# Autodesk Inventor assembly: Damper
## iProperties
Shininess: 20.0
Length Units: 11269
Angle Units: 11279
Time Units: 11290
Mass Units: 11283
Length Display Precision: 3
Angle Display Precision: 2
Created: 2001-04
Part Number: Damper
Document SubType Name: Baugruppe
Designer: dl
Density: 0.0
Volumn: 0.0
Area: 0.0
PropertySet Name: Model Information
Control State: 0
Master: False
Checked Out: False
Author: dl
